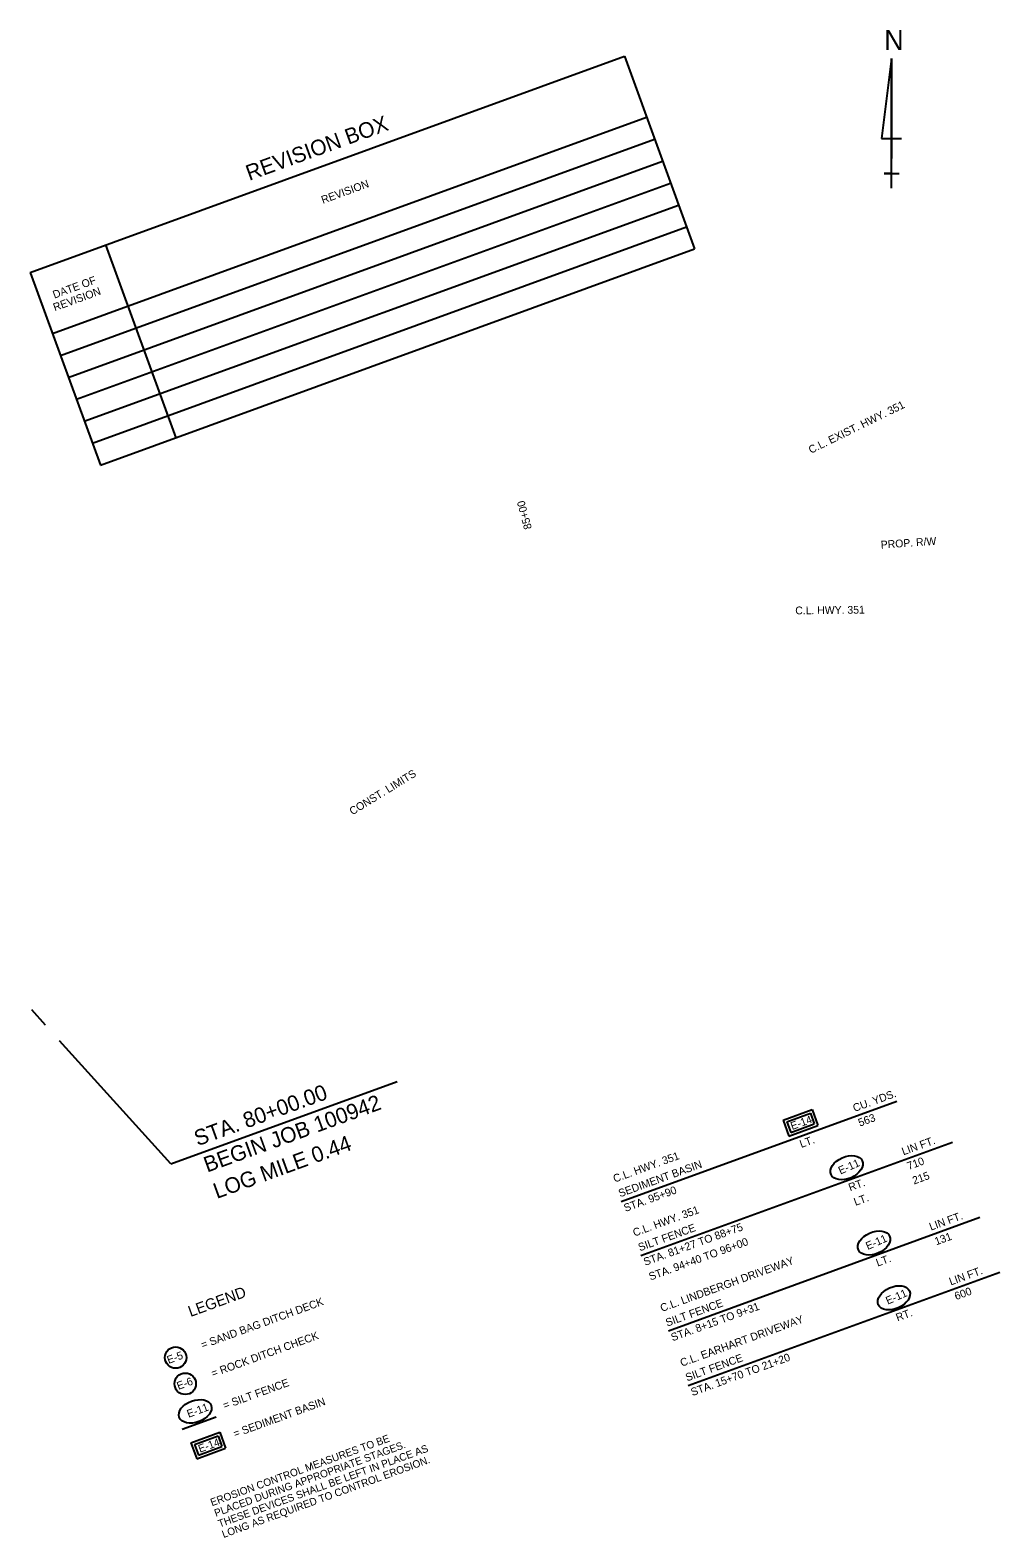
# Model space of a CAD drawing. Extents: x 1710835 to 1712392, y 548501 to 549912.
# Drawn here: x 1710835 to 1711582, y 548501 to 549662 of the extents above; entities that cross this region are included whole.
import ezdxf

# ---------------------------------------------------------------- set-up
doc = ezdxf.new("R2010")
doc.units = 0
for name, color, linetype in [('R_Annotation', 7, 'Continuous'), ('R_Border Notes', 7, 'Continuous'), ('R_Erosion', 7, 'Continuous'), ('R_Horz Alg Annot', 7, 'Continuous'), ('R_ROW Annot', 7, 'Continuous')]:
    doc.layers.add(name, color=color, linetype=linetype)

msp = doc.modelspace()

# ---------------------------------------------------------------- linework, layer by layer
at = {"layer": 'R_Annotation'}
for p, q in [((1710835.2, 549475.2), (1711292.7, 549641.7)), ((1711292.7, 549641.7), (1711346.7, 549493.3)), ((1710852.3, 549428.2), (1711309.8, 549594.7)), ((1710858.5, 549411.3), (1711315.9, 549577.8)), ((1710864.6, 549394.4), (1711322.1, 549560.9)), ((1710870.8, 549377.5), (1711328.2, 549544)), ((1710876.9, 549360.6), (1711334.4, 549527.1)), ((1710883.1, 549343.7), (1711340.5, 549510.2)), ((1710889.3, 549326.8), (1711346.7, 549493.3)), ((1710893.3, 549496.4), (1710947.3, 549347.9)), ((1710835.2, 549475.2), (1710889.3, 549326.8)), ((1710943.6, 548788.9), (1711117.8, 548852.3)), ((1711290.3, 548759.9), (1711502.4, 548837.1)), ((1711414.9, 548822.5), (1711437.2, 548830.6)), ((1711417.8, 548821.2), (1711435.9, 548827.7)), ((1711435.9, 548827.7), (1711438.9, 548819.6)), ((1711437.2, 548830.6), (1711441.7, 548818.2)), ((1711414.9, 548822.5), (1711419.4, 548810.1)), ((1711417.8, 548821.2), (1711420.8, 548813)), ((1711419.4, 548810.1), (1711441.7, 548818.2)), ((1711420.8, 548813), (1711438.9, 548819.6)), ((1711305.4, 548718.3), (1711545.3, 548805.6)), ((1711326.6, 548660.3), (1711566.4, 548747.6)), ((1711341.9, 548618.1), (1711581.8, 548705.4))]:
    msp.add_line(p, q, dxfattribs=at)
for points in [[(1710847.1, 548895.6), (1710836.5, 548907.3)], [(1710943.6, 548788.9), (1710857.9, 548883.6)]]:
    msp.add_lwpolyline(points, dxfattribs=at)
at = {"layer": 'R_Border Notes'}
for p, q in [((1711498.4, 549640), (1711490.7, 549578.4)), ((1711498.4, 549540), (1711498.4, 549640)), ((1711498.4, 549640), (1711498.4, 549563)), ((1711490.7, 549578.4), (1711506.1, 549578.4)), ((1711498.4, 549540), (1711498.4, 549563)), ((1711498.4, 549551.5), (1711492.7, 549551.5)), ((1711492.7, 549551.5), (1711504.2, 549551.5)), ((1711498.4, 549540), (1711498.4, 549551.5))]:
    msp.add_line(p, q, dxfattribs=at)
at = {"layer": 'R_Erosion'}
for p, q in [((1710959, 548574), (1710981.2, 548582.1)), ((1710981.2, 548582.1), (1710985.7, 548569.8)), ((1710959, 548574), (1710963.5, 548561.7)), ((1710961.8, 548572.7), (1710979.9, 548579.3)), ((1710961.8, 548572.7), (1710964.8, 548564.5)), ((1710963.5, 548561.7), (1710985.7, 548569.8)), ((1710964.8, 548564.5), (1710982.9, 548571.1)), ((1710979.9, 548579.3), (1710982.9, 548571.1))]:
    msp.add_line(p, q, dxfattribs=at)
msp.add_lwpolyline([(1710952.2, 548584.6), (1710978.4, 548594.1)], dxfattribs=at)
for centre in [(1710947.2, 548639.6), (1710954.6, 548619.4)]:
    msp.add_circle(centre, 8.26, dxfattribs=at)
for centre, major_axis in [((1711463.8, 548785.8), (12, 5.3)), ((1711484.9, 548727.8), (12, 5.3)), ((1711500.2, 548685.6), (12, 5.3)), ((1710962.3, 548598.2), (12.3, 4.5))]:
    msp.add_ellipse(centre, major_axis=major_axis, ratio=0.638788, dxfattribs=at)

# ---------------------------------------------------------------- texts
at = {"layer": 'R_Annotation'}
for s, height, rotation, p in [('REVISION BOX', 12, 20, (1711003.9, 549545.7)), ('REVISION', 6, 20, (1711060.6, 549528)), ('DATE OF', 6, 20, (1710853.9, 549455)), ('REVISION', 6, 20, (1710854.2, 549445.3)), ('C.L. EXIST. HWY. 351', 6, 26.1667, (1711436.3, 549335.5)), ('C.L. HWY. 351', 6, 0.6428, (1711424.3, 549211.9)), ('CONST. LIMITS', 6, 31.5654, (1711083.3, 549057.1)), ('STA. 80+00.00', 12, 20, (1710964.1, 548802.3)), ('BEGIN JOB 100942', 12, 20, (1710971.5, 548782)), ('CU. YDS.', 6, 20, (1711469.9, 548828.7)), ('E-14', 6, 19.9884, (1711421.9, 548814.8)), ('563', 6, 20, (1711474, 548817.4)), ('LOG MILE 0.44', 12, 20, (1710978.9, 548761.7)), ('LT.', 6, 20, (1711428.9, 548801)), ('LIN FT.', 6, 20, (1711507.5, 548795.3)), ('C.L. HWY. 351', 6, 20, (1711285.3, 548774.3)), ('SEDIMENT BASIN', 6, 20, (1711289.4, 548763)), ('710', 6, 20, (1711511.6, 548784)), ('215', 6, 20, (1711515.7, 548772.8)), ('STA. 95+90', 6, 20, (1711293.5, 548751.7)), ('RT. ', 6, 20, (1711466.5, 548767.6)), ('C.L. HWY. 351', 6, 20, (1711300.5, 548732.7)), ('LT.', 6, 20, (1711470.6, 548756.4)), ('STA. 81+27 TO 88+75', 6, 20, (1711308.7, 548710.2)), ('LIN FT.', 6, 20, (1711528.7, 548737.3)), ('SILT FENCE', 6, 20, (1711304.6, 548721.4)), ('STA. 94+40 TO 96+00', 6, 20, (1711312.8, 548698.9)), ('131', 6, 20, (1711532.8, 548726)), ('C.L. LINDBERGH DRIVEWAY', 6, 20, (1711321.6, 548674.7)), ('LT. ', 6, 20, (1711487.7, 548709.6)), ('LIN FT.', 6, 20, (1711544, 548695.1)), ('600', 6, 20, (1711548.1, 548683.8)), ('SILT FENCE', 6, 20, (1711325.7, 548663.4)), ('STA. 8+15 TO 9+31', 6, 20, (1711329.8, 548652.1)), ('RT. ', 6, 20, (1711503, 548667.4)), ('C.L. EARHART DRIVEWAY', 6, 20, (1711336.9, 548632.5)), ('SILT FENCE', 6, 20, (1711341, 548621.2)), ('STA. 15+70 TO 21+20', 6, 20, (1711345.1, 548609.9))]:
    msp.add_text(s, height=height, rotation=rotation, dxfattribs=at).set_placement(p)
at = {"layer": 'R_Border Notes'}
msp.add_text('N', height=15.4, dxfattribs=at).set_placement((1711492.8, 549646.4))
at = {"layer": 'R_Erosion'}
for s, height, rotation, p in [('E-11', 6, 23.8359, (1711459, 548780.5)), ('E-11', 6, 23.8359, (1711480.1, 548722.4)), ('LEGEND', 8.44, 20, (1710958.7, 548670.8)), ('= SAND BAG DITCH DECK', 6, 20, (1710968, 548646.3)), ('E-11', 6, 23.8359, (1711495.5, 548680.3)), ('= ROCK DITCH CHECK', 6, 20, (1710976, 548624.4)), ('E-5 ', 6, 20, (1710941.8, 548634.7)), ('E-6 ', 6, 20.4005, (1710949.4, 548614.7)), ('= SILT FENCE', 6, 20, (1710985, 548599.7)), ('E-11', 6, 20.2144, (1710957.2, 548593.2)), ('= SEDIMENT BASIN', 6, 20, (1710992.9, 548577.9)), ('E-14', 6, 19.9884, (1710965.9, 548566.3)), ('EROSION CONTROL MEASURES TO BE', 5.769, 20, (1710975.2, 548525.1)), ('PLACED DURING APPROPRIATE STAGES. ', 5.769, 20, (1710978.2, 548516.9)), ('THESE DEVICES SHALL BE LEFT IN PLACE AS ', 5.769, 20, (1710981.1, 548508.7)), ('LONG AS REQUIRED TO CONTROL EROSION.', 5.769, 20, (1710984.1, 548500.6))]:
    msp.add_text(s, height=height, rotation=rotation, dxfattribs=at).set_placement(p)
at = {"layer": 'R_Horz Alg Annot'}
msp.add_text('85+00', height=6, rotation=104.9919, dxfattribs=at).set_placement((1711221.5, 549278.2))
at = {"layer": 'R_ROW Annot'}
msp.add_text('PROP. R/W', height=6, rotation=3.9642, dxfattribs=at).set_placement((1711490.3, 549262.5))

doc.saveas('drawing.dxf')
